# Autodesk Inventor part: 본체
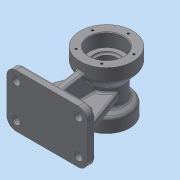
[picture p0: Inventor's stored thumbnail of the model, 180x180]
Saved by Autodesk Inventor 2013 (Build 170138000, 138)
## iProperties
Created: 2015-08
Part Number: 본체
Material: 일반
Document SubType Name: Modeling
Designer: dgall
Density: 1 g/cm^3
Author: dgall
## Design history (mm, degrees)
sketch "스케치1"
  geometry: L1 (0, 0)-(0, -80); L2 (0, -80)-(-122, -80); L3 (-122, -80)-(-122, 0); L4 (-122, 0)-(0, 0); L5 (-14, -66)-(-108, -66); L6 (-108, -66)-(-108, -14); L7 (-108, -14)-(-14, -14); L8 (-14, -14)-(-14, -66); C1 r 6 at (-14, -66); C2 r 6 at (-14, -14); C3 r 6 at (-108, -14); C4 r 6 at (-108, -66); 4 further points
  constraints: 16 end point, 4 centre point, 4 coincident, 4 midpoint, 4 parallel, 2 perpendicular, 1 horizontal, 1 horizontal alignment, 1 vertical, 1 vertical alignment
  dimensions: "d0" = 80 distance of L1.start L1.end; "d1" = 122 distance of L1.end L2.end; "d2" = 94 distance of L5.start L5.end; "d3" = 52 distance of L7.end L5.start; "d4" = 12 diameter of C1; "d5" = 12 diameter of C2; "d6" = 12 diameter of C3; "d7" = 12 diameter of C4
extrude "돌출1" new body sketch "스케치1" distance "d8" = 12; taper "d9" = 0 deg
node "작업 평면1"
sketch "스케치2"
  geometry: L1 (80, 12)-(80, 0) reference; L2 (80, 0)-(0, 0) reference; L3 (0, 0)-(0, 12) reference; L4 (0, 12)-(80, 12) reference; L5 (40, 0)-(40, 90); L6 (0, 90)-(90, 90); L7 (0, 90)-(0, 125); L8 (0, 125)-(20, 125); L9 (20, 125)-(25.774, 115); L10 (25.774, 115)-(52.124, 115); L11 (52.124, 115)-(70, 130); L12 (70, 130)-(90, 130); L13 (90, 130)-(90, 90)
  constraints: 18 end point, 5 perpendicular, 2 parallel, 1 midpoint, 1 vertical alignment
  dimensions: "d10" = 90 distance of L5.start L5.end; "d11" = 90 distance of L6.start L6.end; "d12" = 70 diameter of L8 L6; "d13" = 20 distance of L7.end L8.end; "d14" = 60 deg angle of L10 L9; "d15" = 20 distance of L11.end L12.end; "d16" = 40 deg angle of L10 L11; "d17" = 50 diameter of L10 L6; "d18" = 80 diameter of L12 L6; "d19" = 130 distance between parallel lines of L2 L12
revolve "회전1" sketch "스케치2" stored, may be unused: angle "d20" = 90 deg
sketch "스케치3"
  geometry: C1 r 35 at (0, 0) reference; C2 r 20 at (0, 0); 1 further point
  constraints: 1 centre point, 1 coincident
  dimensions: "d21" = 40 diameter of C2
extrude "돌출2" cut sketch "스케치3" distance "d22" = 17; taper "d23" = 0 deg
sketch "스케치4"
  geometry: C1 r 40 at (0, 0) reference; C2 r 26 at (0, 0); 1 further point
  constraints: 1 centre point, 1 coincident
  dimensions: "d24" = 52 diameter of C2
extrude "돌출3" cut sketch "스케치4" distance "d25" = 20; taper "d26" = 0 deg
sketch "스케치5"
  geometry: C1 r 26 at (0, 0) reference; C2 r 19 at (0, 0); 1 further point
  constraints: 1 centre point, 1 coincident
  dimensions: "d27" = 38 diameter of C2
extrude "돌출4" cut sketch "스케치5" distance "d28" = 3; taper "d29" = 0 deg
sketch "스케치6"
  geometry: C1 r 19 at (0, 0) reference; C2 r 16 at (0, 0); 1 further point
  constraints: 1 centre point, 1 coincident
  dimensions: "d30" = 32 diameter of C2
extrude "돌출5" cut sketch "스케치6" stored distance "d31" = 3; taper "d32" = 0 deg
sketch "스케치7" dims "d33" = 66
  geometry: C1 r 26 at (0, 0) reference; C2 r 40 at (0, 0) reference; 3 further points
  constraints: 2 vertical alignment, 1 coincident, 2 other
hole "구멍1" sketch "스케치7" at (0, 33) diameter "d34" = 3.459; stored, may be unused: countersink angle "d38" = 90 deg, drill point angle "d40" = 118 deg; dims "d35" = 10, "d36" = 4, "d37" = 2, "d39" = 13
sketch "스케치8" dims "d44" = 54
  geometry: C1 r 20 at (0, 0) reference; C2 r 35 at (0, 0) reference; 3 further points
  constraints: 2 vertical alignment, 1 coincident, 2 other
hole "구멍2" sketch "스케치8" at (0, 27) diameter "d45" = 3.459; stored, may be unused: countersink angle "d49" = 90 deg, drill point angle "d51" = 118 deg; dims "d46" = 10, "d47" = 4, "d48" = 2, "d50" = 13
node "작업 평면2"
sketch "스케치10"
  geometry: L1 (0, 0)-(0, 12) reference; L2 (0, 12)-(122, 12) reference; L3 (122, 12)-(122, 0) reference; L4 (122, 0)-(0, 0) reference; L5 (10, 12)-(36.529, 84.887); L6 (112, 12)-(85.471, 84.887); L7 (10, 12)-(112, 12); L8 (31, 36)-(31, 30); L9 (43, 36)-(43, 30); L10 (61, 90)-(61, 0); L11 (79, 36)-(79, 30); L12 (91, 36)-(91, 30); C1 r 16 at (61, 90) reference; A1 r 25 centre (61, 90) between (36.529, 84.887) and (85.471, 84.887); A2 r 6 centre (37, 30) between (31, 30) and (43, 30); A3 r 6 centre (37, 36) between (43, 36) and (31, 36); A4 r 6 centre (85, 36) between (91, 36) and (79, 36); A5 r 6 centre (85, 30) between (79, 30) and (91, 30); 1 further point
  constraints: 16 end point, 10 point on circle, 6 symmetric about line, 5 centre point, 4 tangent, 2 parallel, 1 coincident, 1 horizontal alignment, 1 midpoint, 1 perpendicular, 1 point on line, 5 other
  dimensions: "d61" = 70 deg angle of L2 L5; "d62" = 12 distance between parallel lines of L9 L8; "d64" = 6 distance of A2.centre A3.centre; "d65" = 18 distance from line of L7 A2.centre; "d66" = 48 distance of A5.centre A2.centre; "d67" = 10 distance of L1.end L5.start
extrude "돌출7" join sketch "스케치10" stored distance "d68" = 12; taper "d69" = 0 deg
sketch "스케치11"
  geometry: L1 (17, 110)-(0, 110) reference; L2 (0, 110)-(0, 115.27) reference; L3 (0, 115.27)-(13, 115.27) reference; L4 (13, 115.27)-(14.039, 117) reference; L5 (14.039, 117)-(13, 118.73) reference; L6 (13, 118.73)-(0, 118.73) reference; L7 (0, 118.73)-(0, 125) reference; L8 (0, 125)-(20, 125) reference; L9 (20, 125)-(25.774, 115) reference; L10 (25.774, 115)-(52.124, 115) reference; L11 (52.124, 115)-(70, 130) reference; L12 (70, 130)-(90, 130) reference; L13 (90, 130)-(90, 124.73) reference; L14 (90, 124.73)-(77, 124.73) reference; L15 (77, 124.73)-(75.961, 123) reference; L16 (75.961, 123)-(77, 121.27) reference; L17 (77, 121.27)-(90, 121.27) reference; L18 (90, 121.27)-(90, 116) reference; L19 (90, 116)-(70, 116) reference; L20 (70, 116)-(70, 109) reference; L21 (70, 109)-(67, 109) reference; L22 (67, 109)-(67, 106) reference; L23 (67, 106)-(17, 106) reference; L24 (17, 106)-(17, 110) reference; L25 (80, 12)-(80, 0) reference; L26 (80, 0)-(0, 0) reference; L27 (0, 0)-(0, 12) reference; L28 (0, 12)-(34, 12) reference; L29 (34, 12)-(34, 65) reference; L30 (34, 65)-(25.774, 65) reference; L31 (25.774, 65)-(20, 55) reference; L32 (20, 55)-(0, 55) reference; L33 (0, 55)-(0, 70) reference; L34 (0, 70)-(17, 70) reference; L35 (17, 70)-(17, 74) reference; L36 (17, 74)-(67, 74) reference; L37 (67, 74)-(67, 71) reference; L38 (67, 71)-(70, 71) reference; L39 (70, 71)-(70, 64) reference; L40 (70, 64)-(90, 64) reference; L41 (90, 64)-(90, 50) reference; L42 (90, 50)-(70, 50) reference; L43 (70, 50)-(52.124, 65) reference; L44 (52.124, 65)-(46, 65) reference; L45 (46, 65)-(46, 12) reference; L46 (46, 12)-(80, 12) reference; L47 (10, 12)-(10, 56.907); L48 (10, 56.907)-(17.814, 56.907); L49 (17.814, 56.907)-(23.432, 66.256); L50 (23.432, 66.256)-(55.304, 66.256); L51 (55.304, 66.256)-(72.187, 52.089); L52 (72.187, 52.089)-(77.069, 52.089); L53 (77.069, 52.089)-(70, 12); L54 (70, 12)-(10, 12)
  constraints: 16 end point, 4 parallel, 2 point on line, 1 collinear, 1 perpendicular
  dimensions: "d71" = 10 distance of L27.end L47.start; "d72" = 10 distance of L25.start L53.end; "d73" = 80 deg angle of L46 L53; "d74" = 72.64067 distance between parallel lines of L14 L52; "d75" = 58.47368 distance between parallel lines of L14 L50; "d76" = 67.82263 distance between parallel lines of L14 L48; "d77" = 15.8008 distance between parallel lines of L15 L49; "d78" = 3.00622 distance between parallel lines of L51 L43
extrude "돌출8" join sketch "스케치11" stored distance "d79" = 12; taper "d80" = 0 deg
fillet "모깎기2" dims "d81" = 5
fillet "모깎기3" dims "d82" = 0.3
fillet "모깎기4" dims "d83" = 3
fillet "모깎기5" dims "d84" = 14
sketch "스케치12"
  geometry: L1 (10, 52.119)-(10, 15) reference; L2 (3, 12)-(14, 12) reference; 3 further points
  constraints: 1 other
  dimensions: "d85" = 16 distance from line of L1 point (26, 36); "d86" = 24 distance from line of L2 point (26, 36)
feature "엠보싱1" sketch "스케치12" dims "d0" = 80, "d1" = 122, "d2" = 94, "d3" = 52, "d4" = 12, "d5" = 12, "d6" = 12, "d7" = 12, "d10" = 90, "d11" = 90, "d12" = 70, "d13" = 20, "d14" = 60 deg, "d15" = 20, "d16" = 40 deg, "d17" = 50, "d18" = 80, "d19" = 130, "d87" = 0.5, "d88" = 0
chamfer "모따기1" distance "d89" = 1; stored, may be unused: second distance "d90" = 2, angle "d91" = 45 deg
chamfer "모따기2" distance "d92" = 1; stored, may be unused: second distance "d93" = 2, angle "d94" = 45 deg
node "솔리드1"
pattern_circular "원형 패턴1" dims angle "d42" = 360 deg
pattern_circular "원형 패턴3" dims angle "d96" = 360 deg
node "절단 모서리 투영1"
node "절단 모서리 투영3"
node "절단 모서리 투영4"
